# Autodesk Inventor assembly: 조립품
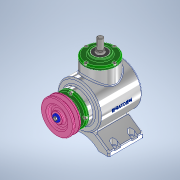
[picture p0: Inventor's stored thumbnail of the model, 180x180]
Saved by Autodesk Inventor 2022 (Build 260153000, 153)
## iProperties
Created: 2023-04
Part Number: 조립품
Document SubType Name: Assembly
Designer: Admin
Author: Admin
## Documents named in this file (17)
- C:\Users\Admin\Desktop\730411V1010\조립품.iam
- C:\Users\Admin\Desktop\730411V1010\본체.ipt
- C:\Users\Admin\Desktop\730411V1010\커버.ipt
- C:\Users\Admin\Desktop\730411V1010\베어링 6203.ipt
- C:\Users\Admin\Desktop\730411V1010\오일실 17 x 32 x 8.ipt
- C:\Users\Admin\Desktop\730411V1010\메인 축.ipt
- 메인 축.ipt
- C:\Users\Admin\Desktop\730411V1010\키 5 x 5 x 14.ipt
- C:\Users\Admin\Desktop\730411V1010\키 4 x 4 x 14.ipt
- C:\Users\Admin\Desktop\730411V1010\메인 베벨기어.ipt
- C:\Users\Admin\Desktop\730411V1010\서브 축.ipt
- 서브 축.ipt
- C:\Users\Admin\Desktop\730411V1010\서브 베벨기어.ipt
- C:\Users\Admin\Desktop\730411V1010\V-벨트풀리.ipt
- C:\Users\Admin\Desktop\730411V1010\볼트 M4 x 10.ipt
- C:\Users\Admin\Desktop\730411V1010\와셔 4 x 16.ipt
- C:\Users\Admin\Desktop\730411V1010\육각볼트 M4 x 8.ipt
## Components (1 placed, 1 different names)
1. V-벨트풀리:1
